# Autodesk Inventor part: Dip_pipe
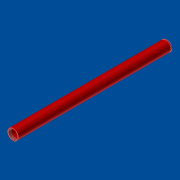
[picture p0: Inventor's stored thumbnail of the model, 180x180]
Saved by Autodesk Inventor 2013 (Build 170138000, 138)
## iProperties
Shininess: 41.0
Length Units: 11269
Angle Units: 11279
Time Units: 11290
Mass Units: 11283
Length Display Precision: 3
Angle Display Precision: 2
Created: 2001-04
Part Number: Dip_pipe
Material: Standard
Document SubType Name: Modellieren
Designer: dl
Density: 1 g/cm^3
Density: 0.0
Volumn: 0.0
Area: 0.0
PropertySet Name: Model Information
Control State: 0
Master: False
Checked Out: False
Author: dl
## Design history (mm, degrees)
body "Solid1"
sketch "Sketch1"
  geometry: C1 r 17.5 at (0, 0); C2 r 15.9 at (0, 0)
  constraints: 2 centre point, 1 coincident
  dimensions: "d0" = 35 diameter of C1; "d1" = 31.8 diameter of C2
extrude "Extrusion1" new body sketch "Sketch1" distance "d2" = 507; taper "d3" = 0 deg
thread "Thread1" dims "d4" = 10, "d5" = 0
chamfer "Chamfer1" distance "d6" = 4; stored, may be unused: angle "d7" = 5 deg, second distance "d10" = 4
chamfer "Chamfer2" distance "d8" = 0.5; stored, may be unused: second distance "d9" = 0.5, angle "d11" = 45 deg
